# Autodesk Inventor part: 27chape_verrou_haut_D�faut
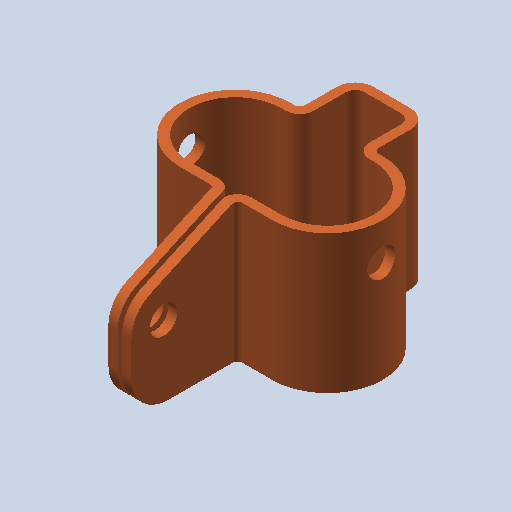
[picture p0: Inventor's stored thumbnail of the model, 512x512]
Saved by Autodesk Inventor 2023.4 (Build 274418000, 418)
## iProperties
Created: 2011-01
Part Number: 27chape_verrou_haut_D�faut
Document SubType Name: Modeling
Designer: eric
Density: 1 g/cm^3
Mass: 9.58977 g
Surface Area: 105.012 cm^2
Volume: 9.58977 cm^3
Material: Générique
Appearance: 255,128,64_1
Author: eric
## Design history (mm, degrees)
feature "Base1"
node "Corps solides"
node "Corps surfaciques"
node "Solide1"
